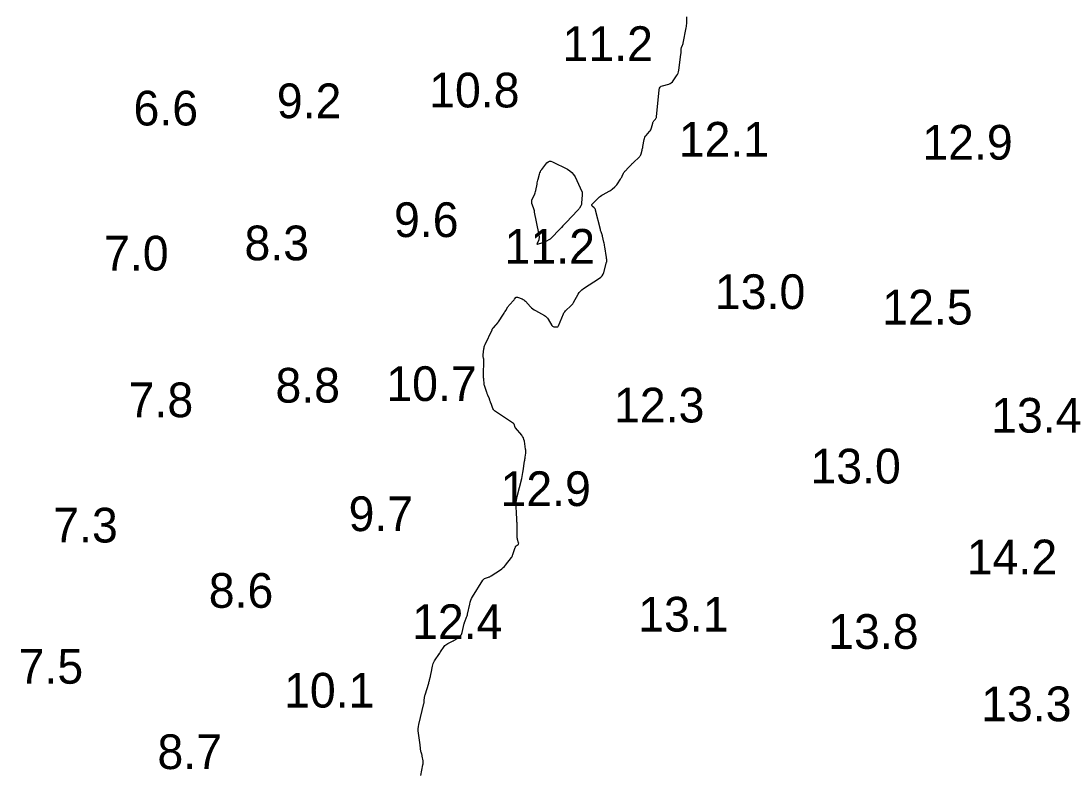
# Model space of a CAD drawing. Extents: x 815352 to 820877, y 582403 to 597439.
# Drawn here: x 820379.8 to 820530.8, y 589822.5 to 589931 of the extents above; entities that cross this region are included whole.
import ezdxf

# ---------------------------------------------------------------- set-up
doc = ezdxf.new("R2010")
doc.units = 0
doc.layers.add('V-CONT-EL12', color=7, linetype='Continuous')
doc.layers.add('V-TOPO-SOUN', color=7, linetype='Continuous')

msp = doc.modelspace()

# ---------------------------------------------------------------- linework, layer by layer
at = {"layer": 'V-CONT-EL12'}
msp.add_lwpolyline([(820437.33, 589822.32), (820437.64, 589823.87), (820437.66, 589824.01), (820437.67, 589824.15), (820437.66, 589824.29), (820437.65, 589824.43), (820437.54, 589825.11), (820437.52, 589825.19), (820437.5, 589825.26), (820437.49, 589825.34), (820437.46, 589825.41), (820437.36, 589825.7), (820437.34, 589825.78), (820437.32, 589825.85), (820437.31, 589825.93), (820437.3, 589826.01), (820437.27, 589826.39), (820437.26, 589826.48), (820437.25, 589826.57), (820437.24, 589826.66), (820437.22, 589826.75), (820436.99, 589828.44), (820436.96, 589828.75), (820436.96, 589829.06), (820436.99, 589829.36), (820437.05, 589829.67), (820437.76, 589832.7), (820437.79, 589832.8), (820437.81, 589832.91), (820437.82, 589833.01), (820437.83, 589833.12), (820437.87, 589833.54), (820437.88, 589833.65), (820437.9, 589833.75), (820437.92, 589833.85), (820437.95, 589833.95), (820438.47, 589835.63), (820438.5, 589835.75), (820438.53, 589835.87), (820438.57, 589835.99), (820438.6, 589836.11), (820438.71, 589836.6), (820438.74, 589836.72), (820438.77, 589836.84), (820438.79, 589836.96), (820438.82, 589837.08), (820439, 589838.08), (820439.05, 589838.28), (820439.12, 589838.48), (820439.2, 589838.66), (820439.31, 589838.84), (820440.02, 589839.88), (820440.03, 589839.9), (820440.05, 589839.92), (820440.06, 589839.94), (820440.07, 589839.97), (820440.11, 589840.05), (820440.13, 589840.07), (820440.14, 589840.09), (820440.15, 589840.11), (820440.17, 589840.13), (820440.71, 589840.91), (820440.81, 589841.03), (820440.93, 589841.15), (820441.06, 589841.24), (820441.2, 589841.33), (820442, 589841.74), (820442.13, 589841.81), (820442.26, 589841.89), (820442.39, 589841.97), (820442.51, 589842.06), (820442.99, 589842.44), (820443.1, 589842.54), (820443.19, 589842.66), (820443.25, 589842.79), (820443.3, 589842.93), (820443.59, 589844.2), (820443.6, 589844.24), (820443.61, 589844.29), (820443.63, 589844.37), (820443.63, 589844.4), (820443.64, 589844.42), (820443.65, 589844.44), (820443.65, 589844.46), (820443.93, 589845.11), (820443.97, 589845.22), (820444.01, 589845.34), (820444.05, 589845.46), (820444.07, 589845.58), (820444.37, 589847.03), (820444.43, 589847.3), (820444.53, 589847.57), (820444.64, 589847.83), (820444.78, 589848.08), (820446.28, 589850.46), (820446.34, 589850.55), (820446.42, 589850.63), (820446.52, 589850.69), (820446.62, 589850.73), (820447.07, 589850.88), (820447.17, 589850.92), (820447.28, 589850.96), (820447.38, 589851.02), (820447.48, 589851.08), (820448.8, 589851.95), (820449.01, 589852.1), (820449.2, 589852.27), (820449.37, 589852.44), (820449.54, 589852.64), (820450.39, 589853.74), (820450.42, 589853.79), (820450.46, 589853.85), (820450.48, 589853.9), (820450.51, 589853.96), (820450.59, 589854.21), (820450.61, 589854.27), (820450.63, 589854.33), (820450.65, 589854.39), (820450.67, 589854.45), (820450.91, 589855.17), (820450.94, 589855.24), (820450.98, 589855.3), (820451.02, 589855.36), (820451.08, 589855.41), (820451.33, 589855.61), (820451.38, 589855.66), (820451.41, 589855.72), (820451.42, 589855.78), (820451.41, 589855.85), (820451.27, 589856.34), (820451.24, 589856.44), (820451.22, 589856.55), (820451.21, 589856.66), (820451.21, 589856.77), (820451.18, 589858.65), (820451.18, 589858.75), (820451.17, 589858.84), (820451.17, 589858.94), (820451.16, 589859.04), (820451.14, 589859.43), (820451.13, 589859.53), (820451.13, 589859.63), (820451.12, 589859.73), (820451.12, 589859.83), (820451.06, 589861.37), (820451.07, 589861.65), (820451.09, 589861.94), (820451.13, 589862.22), (820451.19, 589862.51), (820451.85, 589865.12), (820451.92, 589865.4), (820451.98, 589865.67), (820452.03, 589865.95), (820452.07, 589866.23), (820452.28, 589867.61), (820452.3, 589867.76), (820452.32, 589867.9), (820452.34, 589868.04), (820452.36, 589868.19), (820452.43, 589868.76), (820452.45, 589868.9), (820452.45, 589869.04), (820452.44, 589869.19), (820452.42, 589869.33), (820452.24, 589870.5), (820452.18, 589870.73), (820452.1, 589870.95), (820451.99, 589871.16), (820451.85, 589871.36), (820450.97, 589872.41), (820450.93, 589872.46), (820450.9, 589872.51), (820450.88, 589872.56), (820450.86, 589872.61), (820450.8, 589872.83), (820450.78, 589872.89), (820450.75, 589872.93), (820450.72, 589872.98), (820450.67, 589873.01), (820448.07, 589874.77), (820447.96, 589874.86), (820447.86, 589874.96), (820447.78, 589875.07), (820447.72, 589875.2), (820447.44, 589875.91), (820447.42, 589875.96), (820447.4, 589876.02), (820447.38, 589876.08), (820447.36, 589876.13), (820447.28, 589876.36), (820447.26, 589876.42), (820447.24, 589876.48), (820447.22, 589876.53), (820447.2, 589876.59), (820446.98, 589877.1), (820446.94, 589877.2), (820446.9, 589877.3), (820446.86, 589877.41), (820446.83, 589877.51), (820446.54, 589878.38), (820446.5, 589878.49), (820446.47, 589878.61), (820446.45, 589878.73), (820446.44, 589878.85), (820446.39, 589879.34), (820446.38, 589879.46), (820446.37, 589879.59), (820446.37, 589879.71), (820446.37, 589879.83), (820446.39, 589882.23), (820446.39, 589882.28), (820446.38, 589882.34), (820446.37, 589882.4), (820446.36, 589882.46), (820446.31, 589882.69), (820446.29, 589882.74), (820446.29, 589882.8), (820446.29, 589882.86), (820446.29, 589882.92), (820446.4, 589883.77), (820446.43, 589883.93), (820446.46, 589884.09), (820446.52, 589884.24), (820446.58, 589884.39), (820447.58, 589886.53), (820447.62, 589886.61), (820447.66, 589886.69), (820447.72, 589886.76), (820447.77, 589886.83), (820448.06, 589887.15), (820448.1, 589887.19), (820448.14, 589887.23), (820448.17, 589887.27), (820448.21, 589887.31), (820448.36, 589887.48), (820448.4, 589887.52), (820448.44, 589887.57), (820448.47, 589887.61), (820448.5, 589887.66), (820449.25, 589888.8), (820449.32, 589888.92), (820449.4, 589889.05), (820449.48, 589889.17), (820449.56, 589889.29), (820449.87, 589889.82), (820449.94, 589889.93), (820450.02, 589890.03), (820450.1, 589890.14), (820450.19, 589890.23), (820450.63, 589890.69), (820450.68, 589890.75), (820450.73, 589890.8), (820450.78, 589890.86), (820450.83, 589890.92), (820451.03, 589891.16), (820451.08, 589891.21), (820451.13, 589891.24), (820451.2, 589891.24), (820451.27, 589891.22), (820451.92, 589890.97), (820452.05, 589890.91), (820452.16, 589890.84), (820452.27, 589890.75), (820452.38, 589890.66), (820453.11, 589889.86), (820453.28, 589889.7), (820453.45, 589889.55), (820453.63, 589889.42), (820453.83, 589889.3), (820455.12, 589888.59), (820455.29, 589888.48), (820455.44, 589888.35), (820455.57, 589888.21), (820455.68, 589888.04), (820456.19, 589887.16), (820456.25, 589887.09), (820456.31, 589887.03), (820456.39, 589886.99), (820456.49, 589886.97), (820456.88, 589886.95), (820456.97, 589886.95), (820457.05, 589886.98), (820457.11, 589887.03), (820457.16, 589887.11), (820457.86, 589888.81), (820457.94, 589888.97), (820458.04, 589889.13), (820458.16, 589889.27), (820458.29, 589889.4), (820458.85, 589889.88), (820458.99, 589890.01), (820459.11, 589890.15), (820459.22, 589890.29), (820459.32, 589890.45), (820459.98, 589891.64), (820460.13, 589891.89), (820460.31, 589892.1), (820460.52, 589892.3), (820460.75, 589892.46), (820463.05, 589893.95), (820463.26, 589894.11), (820463.43, 589894.31), (820463.56, 589894.53), (820463.66, 589894.78), (820464.07, 589896.26), (820464.09, 589896.32), (820464.1, 589896.37), (820464.1, 589896.43), (820464.1, 589896.49), (820464.09, 589896.71), (820464.08, 589896.77), (820464.08, 589896.83), (820464.07, 589896.88), (820464.06, 589896.94), (820463.82, 589898.5), (820463.79, 589898.67), (820463.76, 589898.84), (820463.73, 589899.01), (820463.69, 589899.17), (820463.5, 589900.01), (820463.47, 589900.09), (820463.45, 589900.18), (820463.43, 589900.26), (820463.4, 589900.34), (820463.28, 589900.66), (820463.25, 589900.74), (820463.22, 589900.82), (820463.2, 589900.91), (820463.18, 589900.99), (820462.49, 589903.77), (820462.46, 589903.86), (820462.42, 589903.95), (820462.36, 589904.02), (820462.3, 589904.09), (820462.01, 589904.36), (820461.96, 589904.42), (820461.94, 589904.49), (820461.96, 589904.56), (820462.01, 589904.63), (820462.89, 589905.52), (820463.05, 589905.66), (820463.21, 589905.79), (820463.38, 589905.91), (820463.56, 589906.01), (820464.44, 589906.48), (820464.55, 589906.54), (820464.67, 589906.62), (820464.77, 589906.7), (820464.88, 589906.78), (820465.28, 589907.14), (820465.38, 589907.23), (820465.47, 589907.33), (820465.56, 589907.43), (820465.63, 589907.54), (820466.07, 589908.22), (820466.13, 589908.32), (820466.19, 589908.42), (820466.25, 589908.53), (820466.3, 589908.64), (820466.52, 589909.08), (820466.57, 589909.18), (820466.63, 589909.28), (820466.7, 589909.37), (820466.78, 589909.45), (820467.19, 589909.88), (820467.39, 589910.07), (820467.64, 589910.34), (820467.71, 589910.4), (820467.77, 589910.47), (820467.84, 589910.53), (820467.91, 589910.59), (820468.79, 589911.43), (820468.88, 589911.53), (820468.95, 589911.63), (820469.01, 589911.75), (820469.05, 589911.88), (820469.18, 589912.4), (820469.21, 589912.53), (820469.24, 589912.66), (820469.27, 589912.8), (820469.29, 589912.93), (820469.47, 589913.95), (820469.51, 589914.11), (820469.57, 589914.27), (820469.66, 589914.41), (820469.76, 589914.54), (820470.26, 589915.09), (820470.35, 589915.2), (820470.43, 589915.33), (820470.49, 589915.46), (820470.54, 589915.6), (820470.72, 589916.31), (820470.74, 589916.4), (820470.78, 589916.48), (820470.83, 589916.55), (820470.88, 589916.62), (820471.12, 589916.89), (820471.17, 589916.96), (820471.21, 589917.04), (820471.24, 589917.12), (820471.26, 589917.2), (820471.66, 589921.12), (820471.71, 589921.33), (820471.81, 589921.49), (820471.95, 589921.61), (820472.14, 589921.69), (820473.02, 589921.93), (820473.22, 589922.01), (820473.39, 589922.11), (820473.55, 589922.24), (820473.68, 589922.41), (820474.16, 589923.12), (820474.27, 589923.31), (820474.36, 589923.5), (820474.42, 589923.7), (820474.46, 589923.91), (820474.76, 589926.2), (820474.78, 589926.3), (820474.79, 589926.4), (820474.8, 589926.5), (820474.8, 589926.6), (820474.83, 589927.06), (820474.84, 589927.13), (820474.85, 589927.19), (820474.87, 589927.25), (820474.9, 589927.31), (820475.02, 589927.55), (820475.05, 589927.61), (820475.07, 589927.67), (820475.09, 589927.73), (820475.11, 589927.8), (820475.54, 589930.01), (820475.58, 589930.2), (820475.6, 589930.4), (820475.62, 589930.6), (820475.63, 589930.8), (820475.64, 589931.61)], dxfattribs=at)
msp.add_lwpolyline([(820455.33, 589899.23), (820455.23, 589899.19), (820455.14, 589899.15), (820455.04, 589899.11), (820454.24, 589898.85), (820454.15, 589898.83), (820454.1, 589898.85), (820454.09, 589898.9), (820454.11, 589898.99), (820454.36, 589899.56), (820454.38, 589899.59), (820454.38, 589899.62), (820454.39, 589899.65), (820454.39, 589899.68), (820454.4, 589899.8), (820454.4, 589899.83), (820454.4, 589899.86), (820454.4, 589899.89), (820454.4, 589899.92), (820454.37, 589900.21), (820454.37, 589900.27), (820454.36, 589900.32), (820454.35, 589900.38), (820454.34, 589900.44), (820453.71, 589903.49), (820453.68, 589903.65), (820453.64, 589903.81), (820453.59, 589903.96), (820453.54, 589904.12), (820453.33, 589904.73), (820453.29, 589904.88), (820453.29, 589905.04), (820453.31, 589905.18), (820453.37, 589905.33), (820453.68, 589905.96), (820453.75, 589906.12), (820453.81, 589906.28), (820453.86, 589906.44), (820453.89, 589906.61), (820454.07, 589907.52), (820454.1, 589907.7), (820454.14, 589907.88), (820454.18, 589908.06), (820454.23, 589908.24), (820454.41, 589908.96), (820454.47, 589909.13), (820454.54, 589909.3), (820454.63, 589909.46), (820454.73, 589909.61), (820455.48, 589910.56), (820455.65, 589910.73), (820455.84, 589910.82), (820456.05, 589910.82), (820456.27, 589910.74), (820458.46, 589909.65), (820458.8, 589909.45), (820459.09, 589909.2), (820459.33, 589908.91), (820459.53, 589908.57), (820460.52, 589906.46), (820460.54, 589906.42), (820460.55, 589906.38), (820460.56, 589906.34), (820460.56, 589906.3), (820460.57, 589906.13), (820460.57, 589906.09), (820460.57, 589906.04), (820460.57, 589906), (820460.57, 589905.96), (820460.47, 589904.76), (820460.46, 589904.66), (820460.44, 589904.57), (820460.41, 589904.49), (820460.36, 589904.4), (820460.18, 589904.07), (820460.13, 589903.99), (820460.07, 589903.92), (820460.01, 589903.84), (820459.95, 589903.77), (820458.24, 589901.99), (820458.01, 589901.75), (820457.78, 589901.51), (820457.56, 589901.27), (820457.33, 589901.03), (820456.1, 589899.74), (820456.03, 589899.67), (820455.95, 589899.6), (820455.87, 589899.54), (820455.78, 589899.48), (820455.42, 589899.28)], close=True, dxfattribs=at)

# ---------------------------------------------------------------- texts
at = {"layer": 'V-TOPO-SOUN'}
for s, p in [('11.2 ', (820457.73, 589925.25)), ('10.8 ', (820438.53, 589918.56)), ('9.2', (820416.6, 589917.01)), ('6.6', (820395.97, 589915.96)), ('12.1 ', (820474.46, 589911.47)), ('12.9 ', (820509.53, 589911.04)), ('9.6', (820433.47, 589899.89)), ('8.3', (820411.94, 589896.54)), ('11.2 ', (820449.39, 589896.05)), ('7.0', (820391.73, 589895.07)), ('13.0 ', (820479.67, 589889.52)), ('12.5 ', (820503.76, 589887.29)), ('8.8', (820416.4, 589876.04)), ('10.7 ', (820432.36, 589876.27)), ('7.8', (820395.27, 589873.94)), ('12.3 ', (820465.14, 589873.18)), ('13.4 ', (820519.44, 589871.71)), ('13.0 ', (820493.42, 589864.39)), ('12.9 ', (820448.8, 589861.14)), ('9.7', (820426.93, 589857.53)), ('7.3', (820384.41, 589855.89)), ('14.2 ', (820515.93, 589851.3)), ('8.6', (820406.8, 589846.48)), ('13.1 ', (820468.62, 589843.06)), ('12.4 ', (820436.07, 589841.98)), ('13.8 ', (820495.98, 589840.57)), ('7.5', (820379.43, 589835.55)), ('10.1 ', (820417.64, 589832.11)), ('13.3 ', (820517.99, 589830.14)), ('8.7', (820399.41, 589823.25))]:
    msp.add_text(s, height=5, dxfattribs=at).set_placement(p)

doc.saveas('drawing.dxf')
